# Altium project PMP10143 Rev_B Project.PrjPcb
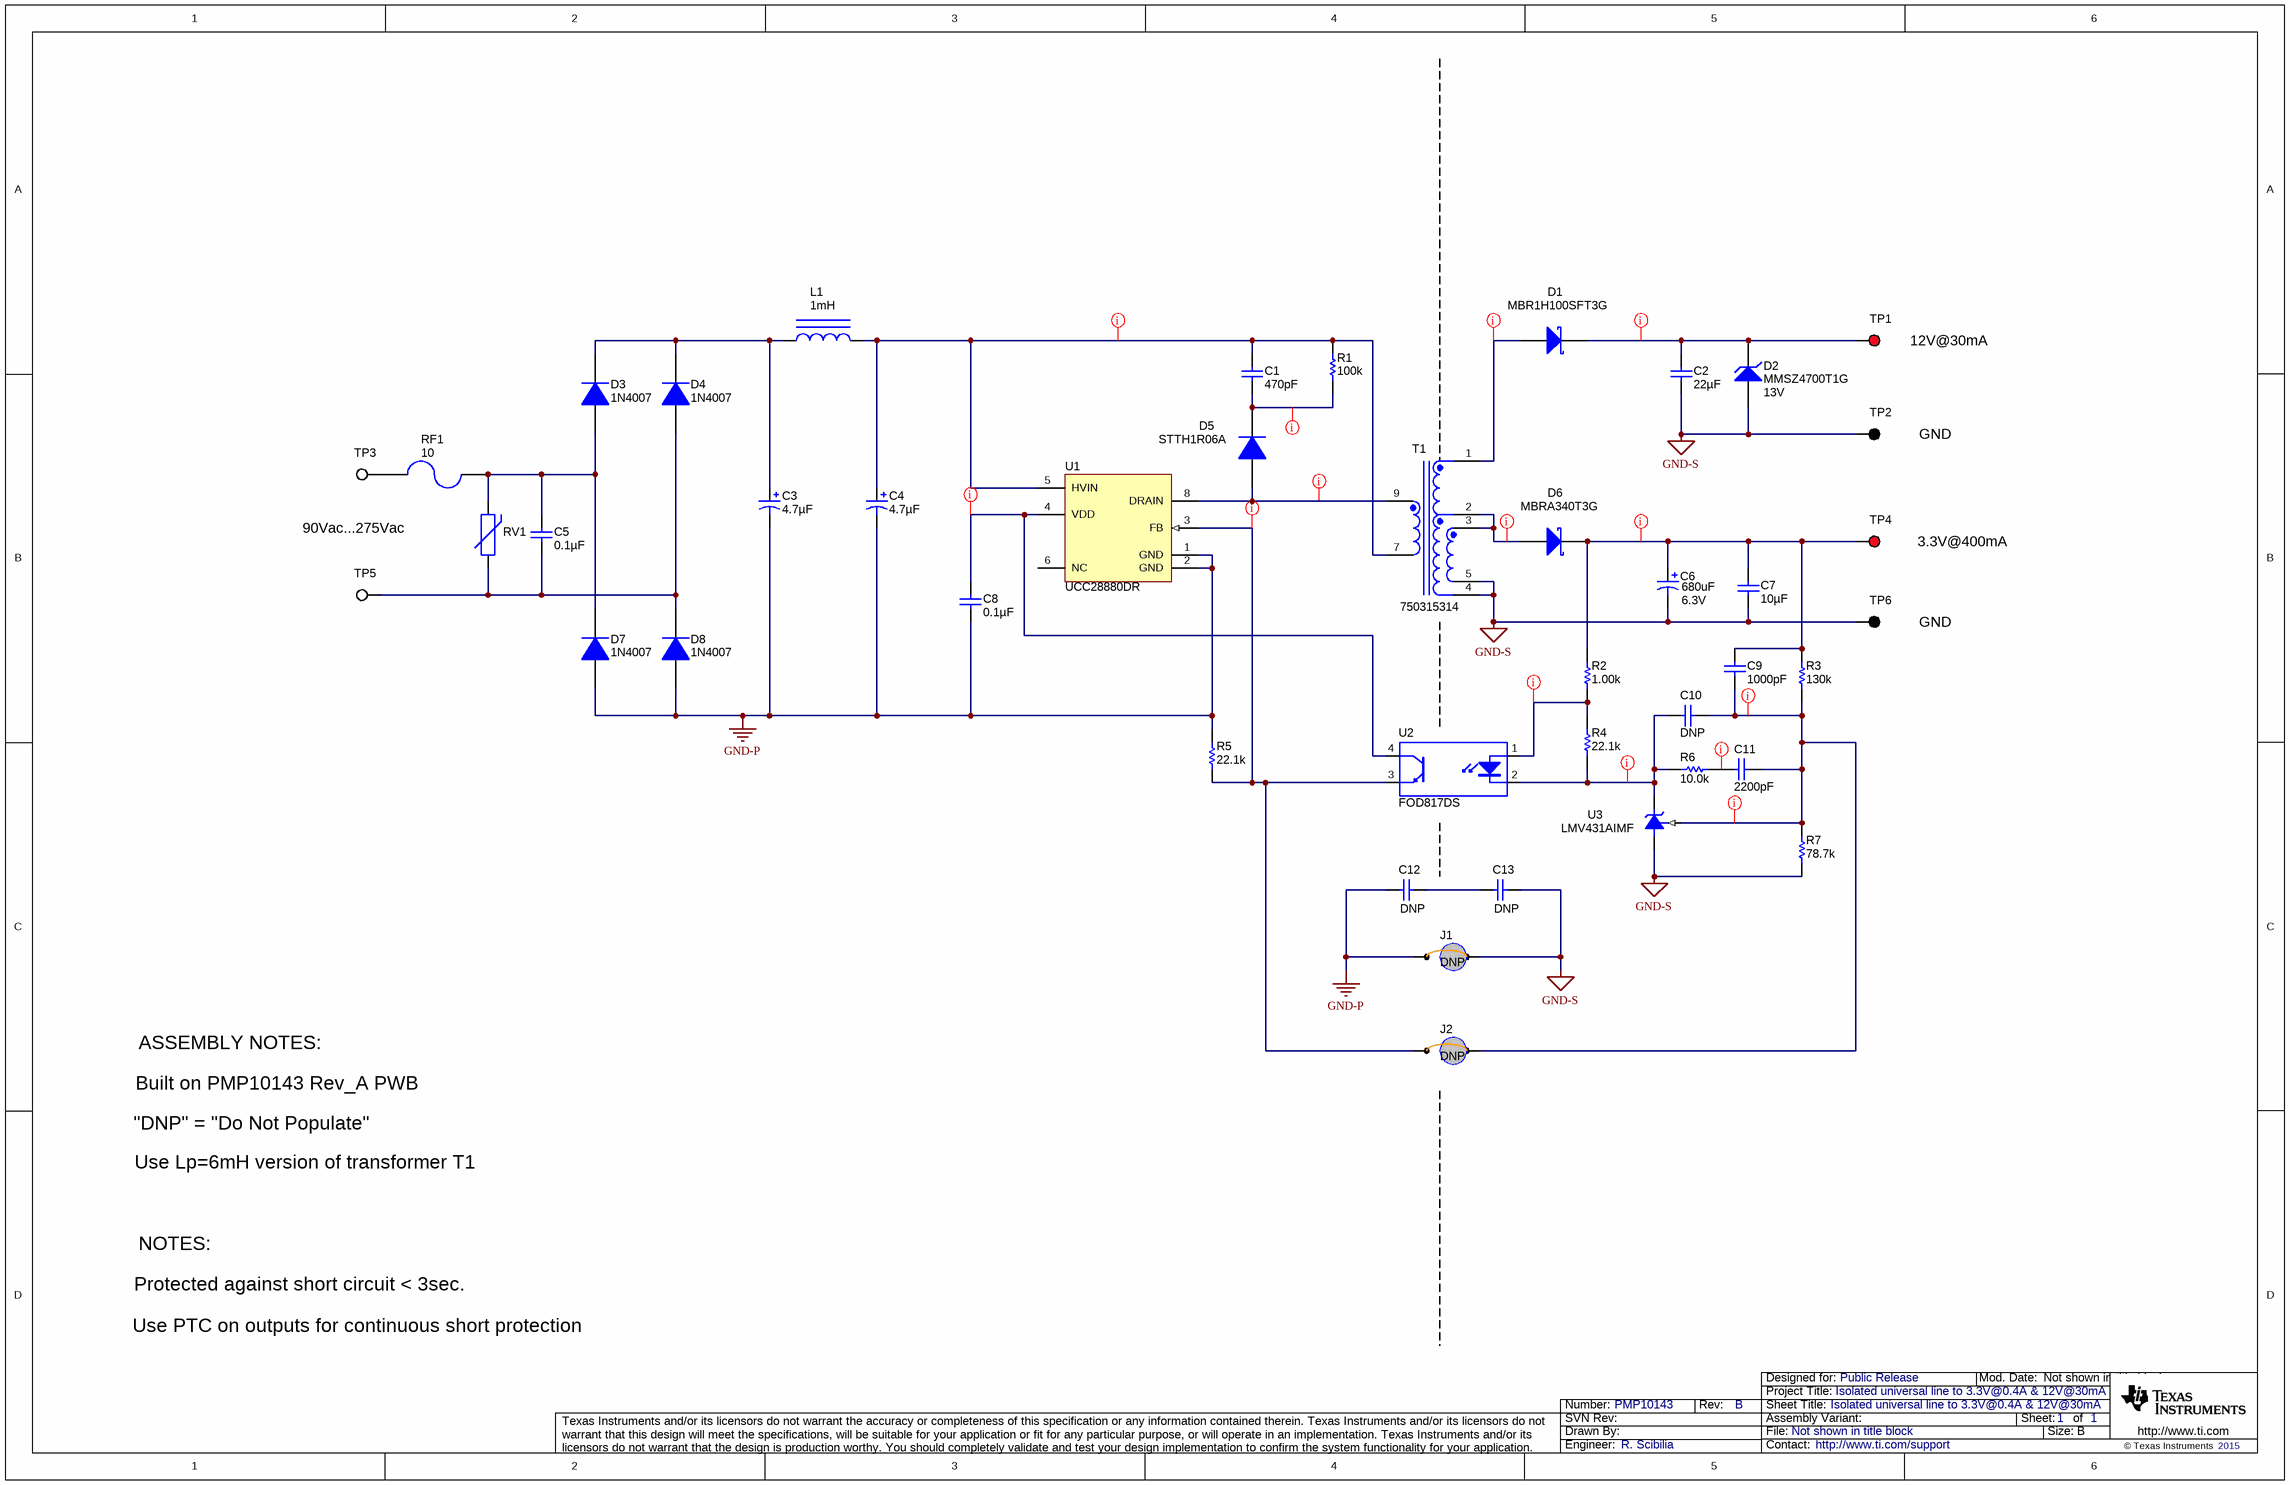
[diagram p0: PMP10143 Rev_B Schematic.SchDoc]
CopyrightYear: 2015; PCB_Layout: R. Scibilia; PCB_Rev: A; PRJ_Customer: Public Release; PRJ_Engineer: R. Scibilia; PRJ_Number: PMP10143; PRJ_Title: Isolated universal line to 3.3V@0.4A & 12V@30mA; SCH_Rev: B; TechSupport: http://www.ti.com/support
1 sheet, 43 parts. Net scope: global (net labels, ports and power ports of the same name join across sheets).

## Sheet PMP10143 Rev_B Schematic.SchDoc: Isolated universal line to 3.3V@0.4A & 12V@30mA
size 431 x 279 mm; Date: Not shown in title block; ApprovedBy: Not shown in title block; CheckedBy: Not shown in title block; Author: Not shown in title block; CompanyName: Not shown in title block; Engineer: Not shown in title block; Organization: Not shown in title block; Address1: Not shown in title block; Address2: Not shown in title block; Address3: Not shown in title block; Address4: Not shown in title block; DocumentNumber: 1; Revision: Use project parameter SCH_Rev; SheetNumber: 1; SheetTotal: 1; PageSetup: Record=PageOptions¦CenterHorizontal=True¦CenterVertical=True¦PrintScale=1.00¦XCorrection=1.00¦YCorrection=1.00¦PrintKind=0¦BorderSize=5000000¦LeftOffset=0¦BottomOffset=0¦Orientation=2¦PaperLength=1000¦PaperWidth=1000¦Scale=100¦PaperSource=15¦PrintQuality=600¦MediaType=1¦DitherType=10¦PaperKind=Letter¦PrintScaleMode=1

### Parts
C1  ValueDisplayed: 470pF  [1206]  (hidden comment: C3216C0G2J471J)
C2  ValueDisplayed: 22µF  [1210]  (hidden comment: C3225X7R1C226M)
C3  ValueDisplayed: 4.7µF  [ESH_10x15]  (hidden comment: ESH475M450AH2AA)
C4  ValueDisplayed: 4.7µF  [ESH_10x15]  (hidden comment: ESH475M450AH2AA)
C5  ValueDisplayed: 0.1µF  [CAPRR1500W60L1750T550H1250]  (hidden comment: ECQ-U2A104ML)
C6  value 680uF  Value2: 6.3V  [CAPSMT_6_D3L]  (hidden comment: 6TPE680MI)
C7  ValueDisplayed: 10µF  [0805_HV]  (hidden comment: C2012X7R0J106M125AB)
C8  ValueDisplayed: 0.1µF  [0603]  (hidden comment: C1608X7R1H104K)
C9  ValueDisplayed: 1000pF  [0603]  (hidden comment: C1608C0G1H102J)
C10  DNP  [0603]
C11  ValueDisplayed: 2200pF  [0603]  (hidden comment: C1608X7R1H222K)
C12  DNP  [CAPRD500W60D800H850]
C13  DNP  [CAPRD500W60D800H850]
D1  MBR1H100SFT3G  [SOD-123FL]
D2  MMSZ4700T1G  value 13V  [SOD-123]
D3  1N4007  [DO-41]
D4  1N4007  [DO-41]
D5  STTH1R06A  [SMA]
D6  MBRA340T3G  [SMA]
D7  1N4007  [DO-41]
D8  1N4007  [DO-41]
J1  DNP  [923345-03-C]
J2  DNP  [923345-03-C]
L1  value 1mH  [IND_WE-TI_XS]  (hidden comment: 7447462102)
R1  ValueDisplayed: 100k  [1206]  (hidden comment: CRCW1206100KJNEA)
R2  ValueDisplayed: 1.00k  [0603]  (hidden comment: CRCW06031K00FKEA)
R3  ValueDisplayed: 130k  [0603]  (hidden comment: CRCW0603130KFKEA)
R4  ValueDisplayed: 22.1k  [0603]  (hidden comment: CRCW060322K1FKEA)
R5  ValueDisplayed: 22.1k  [0603]  (hidden comment: CRCW060322K1FKEA)
R6  ValueDisplayed: 10.0k  [0603]  (hidden comment: CRCW060310K0FKEA)
R7  ValueDisplayed: 78.7k  [0603]  (hidden comment: CRCW060378K7FKEA)
RF1  ValueDisplayed: 10  [RES_PWR4522]  (hidden comment: PWR4522AS10R0JA)
RV1  S10K275E2  [VAR_S10K275E2]  (value not drawn)
T1  750315314  [Wurth_750315314]
TP1  5000  [Keystone5000]  (value not drawn)
TP2  5001  [Keystone5001]  (value not drawn)
TP3  5002  [Keystone5002]  (value not drawn)
TP4  5000  [Keystone5000]  (value not drawn)
TP5  5002  [Keystone5002]  (value not drawn)
TP6  5001  [Keystone5001]  (value not drawn)
U1  UCC28880DR  [D0007A_N]
U2  FOD817DS  [N04C]
U3  LMV431AIMF  [MF03A_N]

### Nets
GND-P: C3.2(-) C4.2(-) C8.2 C12.2 D7.2(A) D8.2(A) J1.1 R5.2 U1.1(GND) U1.2(GND)
GND-S: C2.2 C6.2(-) C7.2 C13.1 D2.2(A) J1.2 R7.1 T1.4 T1.5 TP2.1 TP6.1 U3.3(A)
NetC1_1: C1.1 C4.1(+) L1.2 R1.2 T1.7 U1.5(HVIN)
NetC1_2: C1.2 D5.1(K) R1.1
NetC2_1: C2.1 D1.1(K) D2.1(K) TP1.1
NetC3_1: C3.1(+) D3.1(K) D4.1(K) L1.1
NetC5_1: C5.1 D3.2(A) D7.1(K) RF1.1 RV1.2
NetC5_2: C5.2 D4.2(A) D8.1(K) RV1.1 TP5.1
NetC6_1: C6.1(+) C7.1 C9.1 D6.1(K) R2.2 R3.2 TP4.1
NetC8_1: C8.1 U1.4(VDD) U2.4(C)
NetC9_2: C9.2 C10.2 C11.1 J2.2 R3.1 R7.2 U3.1(REF)
NetC10_1: C10.1 R4.1 R6.1 U2.2(K) U3.2(K)
NetC11_2: C11.2 R6.2
NetC12_1: C12.1 C13.2
NetD1_2: D1.2(A) T1.1
NetD5_2: D5.2(A) T1.9 U1.8(DRAIN)
NetD6_2: D6.2(A) T1.2 T1.3
NetJ2_1: J2.1 R5.1 U1.3(FB) U2.3(E)
NetR2_1: R2.1 R4.2 U2.1(A)
NetRF1_2: RF1.2 TP3.1

Not connected (* = marked no-connect by the designer): U1 6(NC)

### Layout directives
rule Clearance Constraint [Clearance = 40mil]: NetC1_1, NetC1_2, NetD5_2
rule Clearance Constraint [Clearance = 10mil]: NetC2_1, NetC6_1, NetC8_1, NetC9_2, NetC10_1, NetC11_2, NetD1_2, NetD6_2, NetJ2_1, NetR2_1

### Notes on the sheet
- (near TP1) 12V@30mA
- GND
- 90Vac...275Vac
- 3.3V@400mA
- ASSEMBLY NOTES:
- Built on PMP10143 Rev_A PWB
- "DNP" = "Do Not Populate"
- Use Lp=6mH version of transformer T1
- NOTES:
- Protected against short circuit < 3sec.
- Use PTC on outputs for continuous short protection

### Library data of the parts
C1 = C3216C0G2J471J: CAP, CERM, 470 pF, 630 V, +/- 5%, C0G/NP0, 1206; Manufacturer: TDK; Polarized: N; CompType: Capacitor; Value: 470pF; U/M: EA; Cap_F: 0.00000000047; Tolerance_%: 5; ESR_ohm: 0.1016; Value1: 0.1016 ohm; VDC_V: 630; Value2: 630V; TaMin_C: -55; TaMax_C: 125
C2 = C3225X7R1C226M: CAP, CERM, 22 µF, 16 V, +/- 20%, X7R, 1210; Manufacturer: TDK; Polarized: N; CompType: Capacitor; Value: 22uF; U/M: EA; Cap_F: 0.000022; Tolerance_%: 20; ESR_ohm: 0.002; Value1: 0.002 ohm; VDC_V: 16; Value2: 16V; IRMS_A: 8.11; TaMin_C: -55; TaMax_C: 125
C3 C4 = ESH475M450AH2AA: CAP, AL, 4.7 µF, 450 V, +/- 20%, TH; Manufacturer: Kemet; Polarized: Y; CompType: Capacitor; Value: 4.7uF; U/M: EA; Cap_F: 0.0000047; Tolerance_%: 20; Value1: Unknown; VDC_V: 450; Value2: 450V; IRMS_A: 0.059; TaMin_C: -25; TaMax_C: 105; Cap_Case: 10x15
C5 = ECQ-U2A104ML: CAP, Film, 0.1 µF, 275 V, +/- 20%, TH; Manufacturer: Panasonic; Polarized: N; CompType: Capacitor; Value: 0.1uF; U/M: EA; Cap_F: 0.0000001; Tolerance_%: 20; Value1: Unknown; VDC_V: 275; Value2: 275V; TaMin_C: -40; TaMax_C: 100; Cap_Case: Radial 17.5x5.5x12.5
C6 = 6TPE330ML: CAP, TA, 680 µF, 6.3 V, +/- 20%, 0.018 ohm, SMD; Manufacturer: Panasonic; Polarized: Y; CompType: Capacitor; ValueDisplayed: 680µF; U/M: EA; Cap_F: 0.00068; Tolerance_%: 20; VDC_V: 6.3; ESR_ohm: 0.018; IRMS_A: 2.4; TaMin_C: -55; TaMax_C: 105; Cap_Case: D3L
C7 = C2012X7R0J106M125AB: CAP, CERM, 10 µF, 6.3 V, +/- 20%, X7R, 0805; Manufacturer: TDK; Polarized: N; CompType: Capacitor; Value: 10uF; U/M: EA; Cap_F: 0.00001; Tolerance_%: 20; Value1: Unknown; VDC_V: 6.3; Value2: 6.3V; TaMin_C: -55; TaMax_C: 125; Cap_Case: 0805
C8 = C1608X7R1H104K: CAP, CERM, 0.1 µF, 50 V, +/- 10%, X7R, 0603; Manufacturer: TDK; Polarized: N; CompType: Capacitor; Value: 0.1uF; U/M: EA; Cap_F: 0.0000001; Tolerance_%: 10; ESR_ohm: 0.017; Value1: 0.017 ohm; VDC_V: 50; Value2: 50V; TaMin_C: -55; TaMax_C: 125
C9 = C1608C0G1H102J: CAP, CERM, 1000 pF, 50 V, +/- 5%, C0G/NP0, 0603; Manufacturer: TDK; Polarized: N; CompType: Capacitor; Value: 1000pF; U/M: EA; Cap_F: 0.000000001; Tolerance_%: 5; ESR_ohm: 0.0563; Value1: 0.0563 ohm; VDC_V: 50; Value2: 50V; TaMin_C: -55; TaMax_C: 125
C10 = C1608C0G1H102J: Do Not Populate; Manufacturer: TDK; Polarized: N; CompType: Capacitor; ValueDisplayed: 1000pF; U/M: EA; Cap_F: 0.000000001; Tolerance_%: 5; ESR_ohm: 0.0563; Value1: 0.0563 ohm; VDC_V: 50; Value2: 50V; TempCo: C0G/NP0; TaMin_C: -55; TaMax_C: 125
C11 = C1608X7R1H222K: CAP, CERM, 2200 pF, 50 V, +/- 10%, X7R, 0603; Manufacturer: TDK; Polarized: N; CompType: Capacitor; Value: 2200pF; U/M: EA; Cap_F: 0.0000000022; Tolerance_%: 10; ESR_ohm: 0.145; Value1: 0.145 ohm; VDC_V: 50; Value2: 50V; TaMin_C: -55; TaMax_C: 125
C12 C13 = DE2E3KY222MA2BM01: Do Not Populate; Manufacturer: MuRata; Polarized: N; CompType: Capacitor; ValueDisplayed: 2200pF; U/M: EA; Cap_F: 0.0000000022; Tolerance_%: 20; Value1: Unknown; VDC_V: 250; Value2: 250V; TempCo: E; TaMin_C: -25; TaMax_C: 85
D1 = MBR1H100SFT3G: Diode, Schottky, 100 V, 1 A, SOD-123FL; Manufacturer: ON Semiconductor; U/M: EA; Vf_V: 0.76; Value: 100V; Value1: 1A; Value2: 0.76V; Io_A: 1; Vr_V: 100; TJmax_C: 175; RJC_CperW: 85
D2 = MMSZ4700T1G: Diode, Zener, 13 V, 500 mW, SOD-123; Manufacturer: ON Semiconductor; SymbolCreator: a0412235; U/M: EA; Power_W: 0.5; Vz_V: 13; Value1: 0.5W; RJA_CperW: 340
D3 D4 D7 D8 = 1N4007: Diode, P-N, 1000 V, 1 A, TH; Manufacturer: Fairchild Semiconductor; U/M: EA; Vf_V: 1.1; Value: 1000V; Value1: 1A; Value2: 1.1V; Io_A: 1; Vr_V: 1000; TJmax_C: 175; RJC_CperW: 50
D5 = STTH1R06A: Diode, Ultrafast, 600 V, 1 A, SMA; Manufacturer: ST Microelectronics; U/M: EA; Vf_V: 1; Value: 600V; Value1: 1A; Value2: 1V; Vr_V: 600; TJmax_C: 175; RJC_CperW: 30
D6 = MBRA340T3G: Diode, Schottky, 40 V, 3 A, SMA; Manufacturer: ON Semiconductor; U/M: EA; Vf_V: 0.415; Value: 40V; Value1: 3A; Value2: 0.415V; Io_A: 3; Vr_V: 40; RJC_CperW: 15
J1 J2 = 923345-03-C: Do not populate; Manufacturer: 3M; SymbolCreator: a0412235; CompType: Jumper Wire; U/M: EA
L1 = 7447462102: Inductor, Unshielded Drum Core, Ferrite, 1 mH, 0.25 A, 4.38 ohm, TH; Manufacturer: Wurth Elektronik eiSos; Ind_H: 1.0E-3; Imax_A: 0.25; Irms: 0.25A @ 40C rise; Isat: 0.27A @ 10% inductance drop; DCR_ohm: 4.38; Value2: 0.25A
R1 = CRCW1206100KJNEA: RES, 100 k, 5%, 0.25 W, 1206; Manufacturer: Vishay-Dale; CompType: Resistor; Value: 100k; Res_ohm: 100000; Tolerance_%: 5; Power_W: 0.25; Value2: 0.25W; VDC_V: 200; TempCo: 200 ppm/C; EIA_Code: E24; U/M: EA
R2 = CRCW06031K00FKEA: RES, 1.00 k, 1%, 0.1 W, 0603; Manufacturer: Vishay-Dale; CompType: Resistor; Value: 1.00k; Res_ohm: 1000; Value_Code: 1k00; Tolerance_%: 1; Power_W: 0.1; Value2: 0.1W; VDC_V: 75; TempCo: 100 ppm/C; EIA_Code: E96; U/M: EA
R3 = CRCW0603130KFKEA: RES, 130 k, 1%, 0.1 W, 0603; Manufacturer: Vishay-Dale; CompType: Resistor; Value: 130k; Res_ohm: 130000; Tolerance_%: 1; Power_W: 0.1; Value2: 0.1W; VDC_V: 75; TempCo: 100 ppm/C; EIA_Code: E96; U/M: EA
R4 R5 = CRCW060322K1FKEA: RES, 22.1 k, 1%, 0.1 W, 0603; Manufacturer: Vishay-Dale; CompType: Resistor; Value: 22.1k; Res_ohm: 22100; Value_Code: 22k1; Tolerance_%: 1; Power_W: 0.1; Value2: 0.1W; VDC_V: 75; TempCo: 100 ppm/C; EIA_Code: E96; U/M: EA
R6 = CRCW060310K0FKEA: RES, 10.0 k, 1%, 0.1 W, 0603; Manufacturer: Vishay-Dale; CompType: Resistor; Value: 10.0k; Res_ohm: 10000; Value_Code: 10k0; Tolerance_%: 1; Power_W: 0.1; Value2: 0.1W; VDC_V: 75; TempCo: 100 ppm/C; EIA_Code: E96; U/M: EA
R7 = CRCW060378K7FKEA: RES, 78.7 k, 1%, 0.1 W, 0603; Manufacturer: Vishay-Dale; CompType: Resistor; Value: 78.7k; Res_ohm: 78700; Value_Code: 78k7; Tolerance_%: 1; Power_W: 0.1; Value2: 0.1W; VDC_V: 75; TempCo: 100 ppm/C; EIA_Code: E96; U/M: EA
RF1 = PWR4522AS10R0JA: RES, 10, 5%, 3 W, Fusible, TH; Manufacturer: Bourns; SymbolCreator: a0412235; CompType: Fusible Resistor; Value: 10; Value_Code: 10R0; Tolerance_%: 5; Power_W: 3; Value2: 3W; TempCo: 90 ppm/C; EIA_Code: E24; U/M: EA
RV1 = S10K275E2: Varistor 275V RMS 10MM Radial, TH; Manufacturer: EPCOS Inc; SymbolCreator: a0412235
T1 = 750315314: Transformer, 10 mH, SMT; Manufacturer: Wurth Elektronik eiSos; SymbolCreator: Altium; DCR_Ohm: 10.35; Value: 10 mH; LeakageL: 150 uH; U/M: EA
TP1 TP4 = 5000: Test Point, Miniature, Red, TH; Manufacturer: Keystone; CompType: Test Point Loop; U/M: EA
TP2 TP6 = 5001: Test Point, Miniature, Black, TH; Manufacturer: Keystone; CompType: Test Point Loop; U/M: EA
TP3 TP5 = 5002: Test Point, Miniature, White, TH; Manufacturer: Keystone; CompType: Test Point Loop; U/M: EA
U1 = UCC28880DR: 700-V Lowest Quiescent Current Off-Line Switcher, D0007A; Alternate Manufacturer: None; Manufacturer: Texas Instruments; SymbolCreator: a0411947; CompType: IC; U/M: EA
U2 = FOD817DS: Optocoupler, 5kV RMS, SMT; Manufacturer: Fairchild Semiconductor; U/M: EA
U3 = LMV431AIMF: Low-Voltage (1.24V) Adjustable Precision Shunt Regulator, 3-pin SOT-23; Manufacturer: Texas Instruments; PackageTopMarking: RLA*XTT; PowerWise: N; CompType: MiscPower

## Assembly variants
001: not fitted FID1 FID2 FID3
